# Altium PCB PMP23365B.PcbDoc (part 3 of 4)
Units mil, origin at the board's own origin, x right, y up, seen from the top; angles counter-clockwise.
Board outline 5450 x 2600 mil, 4 copper layers (Top Layer, Signal Layer 1, Signal Layer 2, Bottom Layer), stack 61.2 mil thick; 303 components, 149 nets, 783 pads, 285 vias.
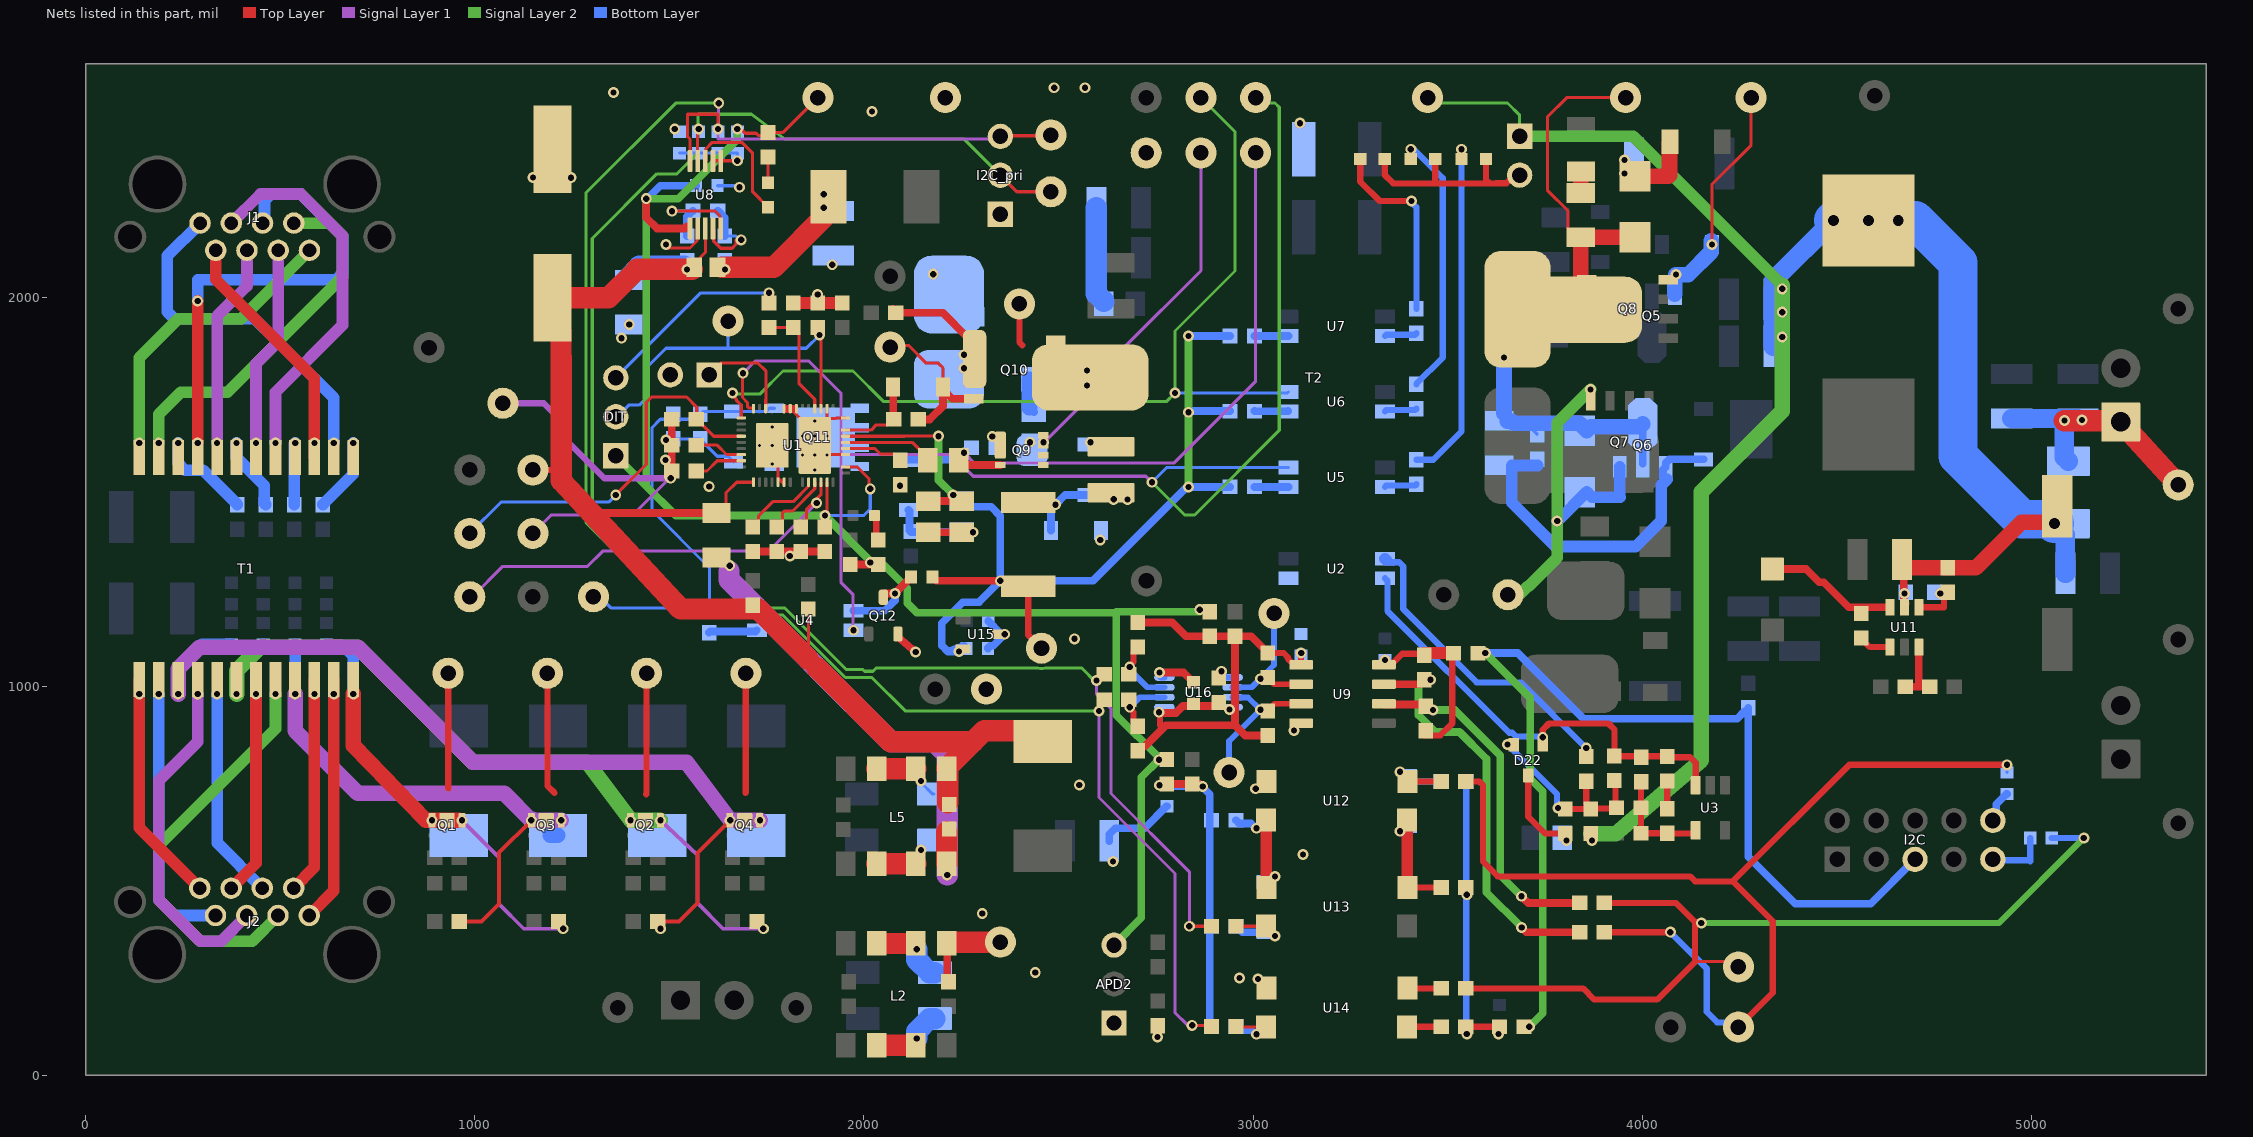
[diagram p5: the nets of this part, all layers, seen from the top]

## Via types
v1: diameter 28, hole 16, Top Layer to Bottom Layer, 261 vias
v2: diameter 19.68, hole 7.87, Top Layer to Bottom Layer, 13 vias
v3: diameter 50, hole 30, Top Layer to Bottom Layer, 7 vias
v4: diameter 50, hole 28, Top Layer to Bottom Layer, 4 vias

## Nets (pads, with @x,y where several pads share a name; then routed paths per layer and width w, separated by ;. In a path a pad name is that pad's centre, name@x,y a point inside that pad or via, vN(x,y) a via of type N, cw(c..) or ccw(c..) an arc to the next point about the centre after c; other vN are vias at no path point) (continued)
NetC31_1: C31.1 Drain_M.1 pad.1@2581.66,1793.73 Q10.5 Q10.6 Q10.7 Q10.8 T2.3 T2.4 | length 109.4
  Top Layer w16: Drain_M.1@2399.67,1982.38 2399.67,1883.48 2407.1,1876.05
  other v1: 2573.44,1773.09 2573.44,1811.67
NetC31_2: C31.2 R122.2 | length 89
  Bottom Layer w20: R122.2@2425.61,1715.82 R122.2@2436.99,1704.44
  Bottom Layer w40: R122.2@2425.61,1715.82 C31.2@2425.61,1788.74
NetC32_1: C32.1 D17.1 Q6.1 R27.1 | length 892.5
  Bottom Layer w8: D17.1@4157.5,1583.03 D17.1@4159.53,1581
  Bottom Layer w20: 4053.48,1521.14 4053.48,1556.45 Q6.1@4060.72,1563.69 4060.72,1573.53 4070.23,1583.03 D17.1@4157.5,1583.03
  Bottom Layer w30: C32.1@3731.35,1567.07 3664.65,1567.07 3664.65,1472.21 3778.01,1358.85 3982.98,1358.85 4048.87,1424.74 4048.87,1516.39 4064.33,1531.85
NetC32_2: C32.2 D12.1 D19.2 Drain_F.1 pad.1@3679.66,1968.61 pad.1@3830,1967.5 Q6.2 Q6.4 Q8.5 Q8.6 Q8.7 Q8.8 R27.2 R29.1 T2.10 T2.11 T2.12 | length 1634.6
  Top Layer w8: R29.1@3842,2153.65 3831.17,2153.65 3809.58,2175.24 3809.58,2221.44 3756.3,2274.72 3756.3,2462.74 3806.06,2512.5 Drain_F.1@3957.5,2512.5
  Top Layer w40: pad.1@3830,1967.5 3842,1972.44 R29.1@3842,2153.65 3842.14,2153.5 3981.54,2153.5 D19.2@3981.68,2153.36
  Bottom Layer w8: R27.2@3644.96,1700.93 3644.96,1682.14 3664.92,1662.18 3715.3,1662.18 3730,1647.48 C32.2@3730,1646.5
  Bottom Layer w20: Q6.2@4001.67,1571.56 Q6.4@4001.67,1673.92
  Bottom Layer w40: R27.2@3644.96,1700.93 v1@3644.96,1842.2 ; R27.2@3653.82,1681.24 3664.65,1681.24 3670.24,1675.65 3838.68,1675.65 3857.5,1656.83 3867.66,1666.99 3994.74,1666.99 Q6.4@4001.67,1673.92
  other v1: 3644.96,1844.49
NetC34_2: C34.2 SST.1 U1.33 | length 1127.7
  Top Layer w8: C34.2@1838.31,1408.99 1853.02,1423.69 1853.02,1455.11 1889.59,1491.69 U1.33@1889.59,1524.28
  Signal Layer 1 w8: SST.1@987.3,1229.93 994.33,1229.93 1072.35,1307.95 1289.84,1307.95 1329.1,1347.21 1754.86,1347.21 v1(1878.63,1470.98)
NetC35_2: C35.2 R29.2 | length 55.1
  Top Layer w40: R29.2@3842,2267.82 3842.09,2267.91 C35.2@3842.66,2322.91
NetC38_1: C38.1 D18.2 Gate_P.1 Q9.4 R31.2 | length 1696.2
  Top Layer w20: C38.1@2243.87,1580.23 2255.67,1568.43 Q9.4@2350.71,1568.43
  Signal Layer 1 w8: v1(2257.57,1599.67) 2283.83,1573.42 2796.61,1573.42 3006.85,1783.66 Gate_P.1@3006.85,2370.57
  Bottom Layer w20: D18.2@2114.59,1581.87 2237.6,1581.87 2255.41,1599.67 v1(2257.57,1599.67)
NetC38_2: C38.2 U1.41 | length 234.3
  Top Layer w8: U1.41@1952.58,1626.64 2123.96,1626.64 2163.87,1586.73 C38.2@2163.87,1580.23
NetC40_2: C40.2 D19.1 R33.1 | length 177.1
  Top Layer w40: D19.1@3981.68,2310.84 4068.5,2310.84 4070.31,2312.64 4070.31,2398.03 C40.2@4071.96,2399.68
  other v1: 3954.64,2317.51 3954.64,2352.18
NetC41_1: C41.1 DIT.2 DTHR.1 U1.3 | length 937.3
  Top Layer w8: C41.1@1881.78,1921.68 1889.59,1913.87 U1.3@1889.59,1713.25
  Bottom Layer w8: DIT.2@1362.5,1692.44 1365.48,1692.44 1395.44,1722.4 1422.6,1722.4 1443.3,1743.1 1443.3,1820.24 1491.43,1868.37 1650.93,1868.37 ; DTHR.1@1650.93,1938.33 1650.93,1868.37 ; v1(1886.03,1902.24) 1852.16,1868.37 1650.93,1868.37
NetC42_2: C42.2 U1.40 | length 153.6
  Top Layer w8: U1.40@1952.58,1610.89 1976.39,1610.89 2028.37,1610.89 2042.62,1596.64 2078.47,1596.64 2093.17,1581.94 C42.2@2093.17,1580.96
NetC44_1: C44.1 C46.1 R47.2 R52.2 U3.4 | length 278.4
  Top Layer w16: C44.1@3997.62,754.74 3997.36,754.48 3997.36,622.59 R52.2@3997.09,622.32 3997.31,622.09 4064.33,622.09 C46.1@4064.55,621.87 4132.8,621.87 4137.6,626.66 U3.4@4137.6,629.74
NetC44_2: C44.2 D22.1 R45.1 R49.1 U2.2 U3.3 | length 1197.7
  Top Layer w16: D22.1@3744.52,849.58 v1(3744.52,868.83) 3744.52,888.09 3760.56,904.13 3913.53,904.13 3928.73,888.94 R45.1@3928.73,820.84 3929.52,820.05 4063.76,820.05 R49.1@4064.55,819.26 4066.07,817.74 4123.13,817.74 4137.6,803.27 U3.3@4137.6,745.89
  Bottom Layer w16: U2.2@3339.02,1277.5 3345.58,1270.93 3345.58,1193.12 3658.46,880.24 3666.19,880.24 3675.31,871.13 3742.23,871.13 v1(3744.52,868.83)
NetC45_2: C45.2 R43.1 | length 66.6
  Top Layer w16: C45.2@2027.32,1438.52 2031.98,1433.86 2031.98,1380.41 R43.1@2036.64,1375.75
NetC46_2: C46.2 R49.2 | length 71.4
  Top Layer w16: C46.2@4064.55,684.86 R49.2@4064.55,756.26
NetC47_1: C47.1 D22.3 R39.1 | length 219
  Top Layer w16: D22.3@3707.12,770.84 3707.12,665.1 3750.8,621.42 R39.1@3802.29,621.42
  other v1: 3805.91,603.62
NetC48_1: C48.1 D26.1 Gate_ex.1 Q11.4 R55.2 R59.2 | length 1170.1
  Bottom Layer w8: Gate_ex.1@1304.91,1229.93 1321.36,1229.93 1349.9,1201.38 1602.3,1201.38 1603.28,1201.38 1603.28,1303.89 1455.37,1451.8 1455.37,1664.48 1476.97,1686.09 1510.38,1686.09 1567.01,1686.09 R59.2@1579.6,1698.68 1586.8,1705.87 D26.1@1664.94,1705.87 1748.69,1705.87 1757.25,1714.44 Q11.4@1770.25,1714.44
NetC49_1: C49.1 R67.1 U8.10 | length 285.5
  Top Layer w8: v1(1507.1,2220.73) 1507.86,2221.48 1617.23,2221.48 1630.08,2208.64 1630.08,2178.23 U8.10@1631.98,2176.32
  Bottom Layer w8: v1(1507.1,2220.73) C49.1@1559.38,2220.73
  Bottom Layer w20: R67.1@1545.74,2156.93 1545.74,2207.1 1559.38,2220.73 1560.13,2221.48 C49.1@1561.12,2221.48
NetC49_2: C49.2 R68.1 U8.9 | length 233.1
  Top Layer w8: U8.9@1612.3,2176.32 1614.2,2174.42 1614.2,2143.21 1631.98,2125.43 1661.31,2125.43 1671.16,2135.28 v1@1671.16,2147.09
  Bottom Layer w8: R68.1@1642.61,2156.93 1670.82,2156.93 1680.66,2147.09 v1(1684.74,2147.09)
  Bottom Layer w20: C49.2@1624.11,2221.48 1625.09,2221.48 1642.61,2203.96 R68.1@1642.61,2156.93
NetC52_1: C52.1 R74.1 R75.1 R94.1 U9.8 | length 459.6
  Top Layer w16: U9.8@3336.3,1055 3355,1055 3383.68,1083.68 3437.14,1083.68 R74.1@3438.7,1085.24 ; R75.1@3438.7,873.5 3481.42,873.5 3512.05,904.13 3512.05,1082.28 R94.1@3515,1085.24
  Top Layer w30: R74.1@3438.7,1085.24 R94.1@3515,1085.24
  other v1: 3339.02,1067.67
NetC53_1: C53.1 C68.1 R26.2 R73.2 R76.2 R89.1 R105.2 R108.2 R109.2 U9.1 U16.1 U16.8 | length 1295
  Top Layer w15: R109.2@2703.8,834.51 2714.89,845.6 2722.5,845.6 ; v1(2758.41,933.02) 2759.94,931.49 2760.9,930.53 2760.9,898.79 2768.29,891.4 ; R73.2@3037.76,1085.24 3078.96,1085.24 3089.56,1074.63 3089.56,1070.44 3105,1055 U9.1@3123.7,1055 v1(3123.7,1085.09)
  Top Layer w20: R108.2@2703.86,1163.7 2792.33,1163.7 2827.79,1128.23 R105.2@2953.7,1128.23 ; 2722.5,845.6 2768.29,891.4 2776.7,899.81 2953.7,899.81 ; v1@2759.94,931.49 2801.96,931.49 2819.72,949.25 R26.2@2903.51,949.25 ; R76.2@3037.76,873.5 2980,873.5 2953.7,899.81 ; R73.2@3037.76,1085.24 3037.76,1086.22 2995.74,1128.23 R105.2@2953.7,1128.23 ; 2953.7,899.81 R105.2@2953.7,1128.23
  other v1: 2939.47,940.14
NetC56_1: C56.1 C57.1 L10.2 OUT.1 VLOAD.1 | length 646.6
  Top Layer w55: v1(5085,1682.5) 5226.55,1682.5 OUT.1@5228.27,1680.77 ; OUT.1@5230,1679.05 OUT.1@5228.27,1680.77 ; VLOAD.1@5377.5,1517.5 5229.92,1678.97 OUT.1@5228.27,1680.77
  Bottom Layer w50: C56.1@4949.52,1688.01 C57.1@5120,1688.01 ; v1(5085,1682.5) 5085,1588.45 L10.2@5095.25,1578.2
  other v1: 5130,1683.96
NetC61_1: C61.1 U11.1 | length 84.2
  Top Layer w16: C61.1@4562.71,1124.1 4562.71,1123.11 4585.27,1100.55 U11.1@4636.59,1100.55
NetC61_2: C61.2 L11.1 U11.6 | length 343
  Top Layer w20: L11.1@4334.46,1301.55 4420.82,1301.55 4455.22,1267.15 4466.91,1267.15 4531.14,1202.92 U11.6@4636.59,1202.92
NetC64_1: C64.1 R95.1 U11.4 | length 106.1
  Top Layer w16: U11.4@4711.39,1202.92 4775.42,1202.92 4775.42,1231.75 R95.1@4784.79,1241.12
  other v1: 4766.09,1238.17
NetC65_1: C65.1 R97.1 R98.1 R102.1 R103.1 R107.2 | length 814.4
  Top Layer w20: R97.1@2778.7,748.5 R107.2@2843.7,748.5 2862.23,748.5 2868.49,742.24 v1(2870.65,742.24)
  Bottom Layer w20: C65.1@2778.7,746.54 2781.46,743.77 2869.12,743.77 v1(2870.65,742.24) 2870.65,740.08 2888.7,722.03 2888.7,130.34 R103.1@2893.5,125.54
  other v1: 2760,745.55
NetC66_1: C66.1 R99.2 R100.2 R101.2 R104.2 | length 778
  Top Layer w8: v1(3630.55,106.3) 3633.5,109.25 R100.2@3633.5,125
  Top Layer w16: R104.2@3546.5,125 R100.2@3633.5,125
  Bottom Layer w16: R101.2@3546.5,755.19 3547.97,753.71 3547.97,107.78 v1(3549.45,106.3)
  Bottom Layer w20: v1(3630.55,106.3) 3632.03,107.78 3632.03,124.51 C66.1@3633.5,125.98
  other v1: 3549.45,463.99
NetD12_2: D12.2 Gate_R.1 Q6.3 Q7.4 | length 925.3
  Top Layer w8: v1(3867.5,1762.84) 3867.5,1733.4 Q7.4@3867.57,1733.32
  Signal Layer 2 w30: Gate_R.1@3670.24,1234.73 3683.77,1234.73 3706.11,1257.08 3708.1,1257.08 3781.57,1330.55 v1(3781.57,1424.27) 3781.57,1676.9 v1(3867.5,1762.84)
  Bottom Layer w30: v1(3781.57,1424.27) 3782.41,1424.27 3857.5,1499.35 3871.22,1485.63 3943.31,1485.63 3942.61,1486.33 Q6.3@3942.61,1563.69
NetD13_2: D13.2 Gate_F.1 Q5.3 Q8.4 | length 604
  Top Layer w8: Q8.4@4071.96,2044.54 4085.25,2057.83 v1(4087,2057.83) ; v1(4179.47,2135) 4179.47,2289.82 4280,2390.35 Gate_F.1@4280,2498.72
  Bottom Layer w40: Q5.3@4084.06,2007.3 4084.06,2042.49 ; v1(4087,2057.83) 4118.99,2057.83 4177.48,2116.31 D13.2@4177.48,2144.53
NetD14_1: D14.1 D15.1 L9.2 | length 234.9
  Top Layer w8: L9.2@2422.41,1472.13 2486.98,1472.13 v1(2492.54,1466.58)
  Bottom Layer w20: D15.1@2480.53,1400.36 2480.53,1454.57 v1(2492.54,1466.58) 2517.65,1491.69 D14.1@2573.44,1491.69
NetD14_2: D14.2 T2.5
  other v1: 2582.05,1626.86
NetD21_1: D21.1 R34.1 U1.43 | length 219.6
  Top Layer w8: U1.43@1952.58,1658.14 2018.53,1658.14 2031.88,1671.49 2062.46,1671.49 R34.1@2076.67,1685.7
  Top Layer w20: D21.1@2074.27,1768.83 2075.47,1767.63 2075.47,1686.89 R34.1@2076.67,1685.7
NetD21_2: D21.2 Gate_M.1 Q10.4 R34.2 | length 426.8
  Top Layer w8: Gate_M.1@2067.44,1871.46 2072.03,1876.05 2114.59,1876.05 2160.34,1830.3 2191.01,1830.3 2203.21,1818.1 D21.2@2203.21,1768.83
  Top Layer w20: R34.2@2139.66,1685.7 2169.19,1685.7 2203.21,1719.72 D21.2@2203.21,1762.82 ; D21.2@2203.21,1768.83 D21.2@2203.21,1762.82 ; Q10.4@2282.3,1738.74 2227.29,1738.74 D21.2@2203.21,1762.82
NetD22_2: D22.2 R36.1 R39.2 R44.2 R45.2 R47.1 | length 507.2
  Top Layer w8: v1(3653.82,850.37) 3654.61,849.58 D22.2@3669.72,849.58
  Top Layer w16: R39.2@3802.29,684.41 R36.1@3867.71,684.41 3867.71,685.4 3856.25,696.86 R44.2@3856.25,756.18 ; R36.1@3869.41,686.11 3927.03,686.11 3931.41,690.5 3931.41,755.17 R45.2@3928.73,757.85
  Bottom Layer w16: v1(3653.82,850.37) 3781.3,722.89 3781.3,689.66 v1(3783.59,687.37)
NetD23_1: D23.1 R60.2 | length 896.2
  Top Layer w8: D23.1@3535.55,2354.89 v1(3535.55,2380)
  Bottom Layer w16: R60.2@3420,1582.05 3463.13,1582.05 3535.55,1654.47 v1(3535.55,2380)
NetD23_2: D23.2 D24.2 D25.2 TPH/TPL/BT.2 | length 535.8
  Top Layer w16: D25.2@3338.43,2354.9 3338.43,2313.71 3360,2292.14 3470.45,2292.14 ; D24.2@3468.48,2354.89 3468.48,2294.11 3470.45,2292.14 ; D23.2@3598.54,2354.89 3598.54,2301.51 3607.92,2292.14 ; TPH/TPL/BT.2@3685.12,2313.38 3672.17,2313.38 3651.27,2292.47 3624.25,2292.47 3623.92,2292.14 3607.92,2292.14 ; 3470.45,2292.14 3607.92,2292.14
NetD24_1: D24.1 R61.2 | length 695.7
  Top Layer w8: D24.1@3405.49,2354.89 v1(3405.49,2380)
  Bottom Layer w16: v1(3405.49,2380) 3413.37,2380 3487.5,2305.87 3487.5,1844.42 3420,1776.92 R61.2@3420,1775.94
NetD25_1: D25.1 R62.2 | length 493
  Top Layer w16: D25.1@3275.43,2354.9 3275.43,2296.66 3325.17,2246.93 v1(3407.27,2246.93)
  Bottom Layer w16: v1(3407.27,2246.93) 3407.27,2243.68 3420,2230.95 R62.2@3420,1969.83
NetD27_1: D27.1 U8.3 | length 325.6
  Top Layer w8: U8.3@1592.61,2349.55 1594.52,2351.45 1594.52,2381.87 1610.1,2397.45 1686.33,2397.45 1714.06,2369.72 1714.06,2270.59 D27.1@1753.54,2231.11
NetD27_2: D27.2 R72.1 | length 74
  Top Layer w8: D27.2@1753.54,2294.11 1753.62,2294.18 R72.1@1753.62,2368.03
NetD29_1: D29.1 R99.1 U12.1 U13.4 | length 260
  Top Layer w8: U13.4@3396.59,483.22 ccw(c3397.89,484.52) U13.4@3397.89,482.69
  Top Layer w16: U13.4@3397.89,482.69 R99.1@3483.5,482.69
  Top Layer w30: U12.1@3395.61,655.72 3396.1,655.23 3396.1,483.72 U13.4@3396.59,483.22
  other v1: 3377.5,627.18
NetD29_2: D29.2 R101.1 R115.2 U12.2 | length 179.1
  Top Layer w16: U12.2@3396.59,755.72 3397.13,755.19 R115.2@3483.5,755.19
  Bottom Layer w16: D29.2@3397.5,769.47 3403.5,769.47 3417.79,755.19 R101.1@3483.5,755.19
  other v1: 3377.5,780
NetD30_1: D30.1 R98.2 U12.4 U13.1 | length 240.4
  Top Layer w30: U12.4@3033.41,655.72 3033.9,655.23 3033.9,483.72 U13.1@3034.39,483.22
  Bottom Layer w20: R98.2@2956.5,655.72 2965.2,647.02 2995.14,647.02 3007.05,635.11 v1(3009.21,635.11) ; D30.1@3028.08,501.39 D30.1@3032.5,496.97
  other v1: 3056.46,511.23
NetD30_2: D30.2 R102.2 R116.1 U13.2 | length 159.2
  Top Layer w8: R116.1@2956.5,383.22 U13.2@3033.41,383.22
  Bottom Layer w20: R102.2@2956.5,383.22 2957.48,383.22 2972.67,368.03 D30.2@3032.5,368.03
  other v1: 3056.46,358.27
NetDIT_3: DIT.3 R30.1 | length 510.6
  Top Layer w8: R30.1@1756.18,1984.68 1756.34,1984.83 v1(1756.34,2010.9)
  Bottom Layer w8: DIT.3@1362.5,1792.44 1580.96,2010.9 v1(1756.34,2010.9)
NetDrain_P_1: Drain_P.1 pad.1@2432.24,1606.16 Q9.5 Q9.6 Q9.7 Q9.8 R122.1 | length 912.4
  Signal Layer 1 w8: v1(2461.83,1626.86) 2463.8,1626.86 2667.76,1830.81 2667.76,1869.4 2866.17,2067.8 Drain_P.1@2866.17,2370.57
  other v1: 2427.17,1626.86
NetEMPS_1: EMPS.1 U1.11 | length 256.5
  Top Layer w8: EMPS.1@1602.5,1800 1633.47,1830.97 1726.76,1830.97 1748.73,1808.99 1748.73,1737.94 1747.86,1737.07 U1.11@1747.86,1721.07
NetI2C_9: I2C.9 R92.1 | length 158.2
  Bottom Layer w16: I2C.9@4901.24,555 4903.74,552.5 4994.88,552.5 4997.38,550 R92.1@4997.38,610
NetI2C_10: I2C.10 R93.2 | length 83.8
  Bottom Layer w20: I2C.10@4901.24,655 4909.84,663.6 4909.84,696.58 4936.52,723.25 R93.2@4937.5,723.25
NetJ1_1: J1.1 T1.2 | length 898.8
  Bottom Layer w30: J1.1@294.21,2190.08 210,2105.87 210,1961.94 227.57,1944.36 435.06,1944.36 637.95,1741.46 v1(637.95,1625)
NetJ1_2: J1.2 T1.3 | length 637.5
  Top Layer w30: J1.2@334.37,2120 334.37,2045.05 587.95,1791.46 v1(587.95,1625) T1.3@587.95,1587.5
NetJ1_3: J1.3 T1.5 | length 964.9
  Signal Layer 1 w30: J1.3@374.53,2190.08 449.45,2265 552.62,2265 660,2157.62 660,1927.53 487.95,1755.48 v1(487.95,1625)
NetJ1_4: J1.4 T1.8 | length 526.8
  Signal Layer 1 w30: v1(337.95,1625) 337.95,1951.65 414.69,2028.39 J1.4@414.69,2120
NetJ1_5: J1.5 T1.9 | length 1207.4
  Top Layer w30: v1(287.95,1625) v1(287.95,1990)
  Bottom Layer w30: v1(287.95,1990) 287.95,2044.71 643.55,2044.71 661.12,2062.29 661.12,2156.5 552.62,2265 477.22,2265 459.65,2247.43 459.65,2194.88 J1.5@454.84,2190.08
NetJ1_6: J1.6 T1.6 | length 518.6
  Signal Layer 1 w30: v1(437.95,1625) 437.95,1828.73 495,1885.78 J1.6@495,2120
NetJ1_7: J1.7 T1.11 | length 936.7
  Signal Layer 2 w30: v1(187.95,1625) 187.95,1698.63 244.8,1755.48 364.7,1755.48 660,2050.78 660,2157.62 627.54,2190.08 J1.7@535.16,2190.08
NetJ1_8: J1.8 T1.12 | length 770.9
  Signal Layer 2 w30: v1(137.95,1625) 137.95,1844.36 237.95,1944.36 399.68,1944.36 J1.8@575.32,2120
NetJ2_1: J2.1 T1.23 | length 632.7
  Top Layer w30: J2.1@574.76,410.9 637.95,474.09 T1.23@637.95,1017.42
  other v1: 637.95,980
NetJ2_2: J2.2 T1.22 | length 558.5
  Top Layer w30: J2.2@534.61,480.98 587.95,534.33 T1.22@587.95,1017.42
  other v1: 587.95,980
NetJ2_3: J2.3 T1.20 | length 1030.5
  Signal Layer 2 w30: v1(487.95,980) 487.95,890.69 187.95,590.69 187.95,451.73 294.68,345 428.55,345 J2.3@494.45,410.9
NetJ2_4: J2.4 T1.17 | length 547.2
  Bottom Layer w30: v1(337.95,980) 337.95,597.32 J2.4@454.29,480.98
NetJ2_5: J2.5 T1.16 | length 867.4
  Signal Layer 1 w30: v1(287.95,980) 287.95,857.24 187.95,757.24 187.95,451.73 294.68,345 348.23,345 J2.5@414.13,410.9
NetJ2_6: J2.6 T1.19 | length 562.9
  Top Layer w30: J2.6@373.98,480.98 437.95,544.96 T1.19@437.95,1017.42
  other v1: 437.95,980
NetJ2_7: J2.7 T1.14 | length 697.9
  Bottom Layer w30: v1(187.95,980) 187.95,451.73 228.89,410.79 333.71,410.79 J2.7@333.82,410.9 J2.7@329.01,415.71
NetJ2_8: J2.8 T1.13 | length 600.9
  Top Layer w30: T1.13@137.95,1017.42 137.95,636.69 J2.8@293.66,480.98
  other v1: 137.95,980
NetL1_1: L1.1 L2.4 R9.2 | length 161.9
  Top Layer w55: R9.2@2047.48,76.99 L1.1@2130.67,76.99
  Bottom Layer w55: v1(2135.62,94.73) 2135.62,112.82 2168.74,145.94 L2.4@2182.52,145.94
NetL2_3: L2.3 L3.1 R12.2 | length 170.5
  Top Layer w55: R12.2@2047.48,338.88 L3.1@2130.67,338.88
  Bottom Layer w55: v1(2135.62,323.87) 2135.62,297.18 2168.74,264.06 L2.3@2182.52,264.06
NetL4_1: L4.1 L5.3 R13.2 | length 186.6
  Top Layer w8: L4.1@2133.09,788.36 2146.99,774.46 v1(2146.99,756.51)
  Top Layer w55: R13.2@2033.33,788.36 L4.1@2133.09,788.36
  Bottom Layer w8: v1(2146.99,756.51) 2146.99,752.67 2177.13,722.53 L5.3@2179.87,722.53
NetL5_4: L5.4 L6.1 R18.2 | length 141.5
  Top Layer w8: L6.1@2133.09,543.47 2146.99,557.37 v1(2146.99,579.46)
  Top Layer w55: R18.2@2033.33,543.47 L6.1@2133.09,543.47
NetQ10_1: pad.1@2218.74,1788.74 pad.1@2284.49,1840.81 Q10.1 Q10.2 Q10.3 R40.2 R42.2 R120.2 | length 246.3
  Top Layer w20: R40.2@2075.34,1969.67 2080.11,1964.91 2080.11,1959.99 2203.15,1959.99 2267.3,1895.84 2267.3,1890.75 2269.31,1888.74 Q10.1@2282.3,1888.74
  other v1: 2257.01,1817.17 2257.01,1851.84
NetQ12_3: Q12.3 R54.1 U4.1 | length 233.3
  Top Layer w20: Q12.3@2049.94,1228.63 2049.94,1236.5 2051.76,1238.31 v1(2079.68,1238.31) 2121.02,1279.66 R54.1@2121.02,1280.64
  Bottom Layer w20: U4.1@1972.98,1193.98 2053.2,1193.98 2079.68,1220.45 v1(2079.68,1238.31)
NetR5_1: R5.1 T1.10 | length 248.4
  Bottom Layer w30: v1(237.95,1625) 237.95,1572.57 255.53,1555 301.87,1555 389.39,1467.48 R5.1@389.39,1466.5
NetR6_1: R6.1 T1.7 | length 190.5
  Bottom Layer w30: v1(387.95,1625) 387.95,1587.05 459.22,1515.78 459.22,1470.2 R6.1@462.92,1466.5 R6.1@462.92,1467.48
NetR7_1: R7.1 T1.4 | length 159.3
  Bottom Layer w30: R7.1@536.46,1466.5 536.46,1622.96 v1(538.5,1625)
NetR8_1: R8.1 T1.1 | length 190.8
  Bottom Layer w30: R8.1@610,1466.5 610,1467.48 687.95,1545.43 v1(687.95,1625)
NetR26_1: R26.1 U16.5 | length 37.5
  Bottom Layer w15: v1(2919.02,1038.54) 2921.5,1036.06 2921.5,1031.91 2930.59,1022.82 U16.5@2947.57,1022.82
NetR30_2: R30.2 R32.2 U1.4 | length 293.9
  Top Layer w8: R30.2@1756.18,1921.68 R32.2@1818.95,1921.68 1833.65,1906.98 1833.65,1777.26 1873.84,1737.07 U1.4@1873.84,1713.25
NetR35_2: R35.2 REF.1 U1.17 | length 995.8
  Top Layer w8: v1(1362.5,1491.69) 1440.72,1569.91 1440.72,1729.16 1454.67,1743.1 1544.51,1743.1 1570.48,1717.13 1570.48,1686.09 1614.18,1642.39 U1.17@1684.87,1642.39
  Bottom Layer w8: REF.1@987.3,1392.85 1067.59,1473.14 1343.95,1473.14 v1(1362.5,1491.69)
NetR37_2: R37.2 U1.21 | length 126.3
  Top Layer w8: R37.2@1569.49,1553.11 1596.98,1553.11 1623.27,1579.4 U1.21@1684.87,1579.4
NetR38_2: R38.2 U1.20 | length 125.6
  Top Layer w8: R38.2@1569.49,1619.6 1622.8,1619.6 1647.12,1595.27 1684.74,1595.27 U1.20@1684.87,1595.14 U1.20@1684.87,1595.27
NetR44_1: R44.1 U2.1 | length 804.7
  Top Layer w8: R44.1@3856.25,819.17 v1(3856.25,841.02)
  Bottom Layer w16: U2.1@3341.73,1324.78 3347.81,1318.71 3375.47,1318.71 3386.24,1307.95 3386.24,1198.44 3574.79,1009.89 3687.38,1009.89 v1(3856.25,841.02)
  Bottom Layer w30: U2.1@3339.02,1327.5 U2.1@3341.73,1324.78
NetR48_1: R48.1 U1.31 | length 205.4
  Top Layer w8: R48.1@1714.88,1408.99 1729.58,1423.69 1729.58,1437.78 1766.1,1474.3 1818.36,1474.3 1857.84,1513.78 1857.84,1524.28 U1.31@1858.1,1524.28
NetR50_2: R50.2 U1.32 | length 168.1
  Top Layer w8: R50.2@1776.63,1408.99 1790.41,1422.77 1790.41,1445.26 1795.09,1449.94 1816.45,1449.94 1873.72,1507.21 1873.72,1524.15 U1.32@1873.84,1524.28
NetR55_1: R55.1 U4.3 | length 125.2
  Bottom Layer w20: R55.1@1602.3,1137.76 1605.41,1140.87 1721.84,1140.87 U4.3@1724.95,1143.98
NetR60_1: R60.1 U5.4 | length 83.8
  Bottom Layer w16: U5.4@3339.02,1512.22 3342.43,1515.64 3416.58,1515.64 R60.1@3420,1519.06
NetR61_1: R61.1 U6.4 | length 83.8
  Bottom Layer w16: U6.4@3339.02,1706.11 3342.43,1709.53 3416.58,1709.53 R61.1@3420,1712.95
NetR62_1: R62.1 U7.4 | length 83.8
  Bottom Layer w16: U7.4@3339.02,1900 3342.43,1903.42 3416.58,1903.42 R62.1@3420,1906.84
NetR63_1: R63.1 U5.1 | length 87.1
  Bottom Layer w20: R63.1@3003.9,1512.22 U5.1@3090.98,1512.22
NetR64_1: R64.1 U6.1 | length 87.8
  Bottom Layer w8: U6.1@3090.15,1706.94 U6.1@3090.98,1706.11
  Bottom Layer w20: R64.1@3003.9,1706.94 3004.31,1706.53 3089.73,1706.53 U6.1@3090.15,1706.94
NetR65_1: R65.1 U7.1 | length 87.1
  Bottom Layer w20: R65.1@3003.9,1900 U7.1@3090.98,1900
NetR74_2: R74.2 R106.1 U9.7 | length 1071.8
  Top Layer w20: U9.7@3336.3,1005 3428.89,1005 3439.9,1016.01 R74.2@3439.9,1016.99 ; v1(3690.33,380.22) 3702.51,368.03 R106.1@3839.59,368.03
  Signal Layer 2 w20: v1@3458.6,1014.04 v1(3456.06,1016.58) 3439.49,1016.58 3425.6,1002.69 3425.6,925.4 3468.48,882.52 3530.72,882.52 3599.78,813.46 3599.78,470.77 v1(3690.33,380.22)
NetR75_2: R75.2 R121.1 U9.6 | length 872.6
  Top Layer w20: U9.6@3336.3,955 3338.11,953.19 3439.58,953.19 R75.2@3444.16,948.61 ; v1(3689.72,460.39) 3707.1,443.01 R121.1@3839.59,443.01
  Signal Layer 2 w20: v1(3462.86,938.77) 3518.72,938.77 3635.55,821.94 3635.55,514.57 v1(3689.72,460.39)
NetR80_1: R80.1 R81.1 R82.1 R83.1 U8.1 U8.2 | length 231.6
  Top Layer w8: U8.2@1612.3,2349.55 1612.96,2350.21 v1(1674.88,2350.21)
  Bottom Layer w8: R83.1@1525.8,2369.89 R82.1@1575.5,2369.89 R81.1@1625.19,2369.89 R80.1@1674.88,2369.89 v1(1674.88,2350.21)
NetR88_1: R88.1 R96.2 U11.3 | length 164.8
  Top Layer w20: R88.1@4676.5,998.7 4710.59,998.7 ; U11.3@4711.39,1100.55 4710.59,1099.75 4710.59,998.7 ; R96.2@4739.07,998.7 4710.59,998.7
NetR103_2: R103.2 R118.1 U14.4 | length 138.6
  Top Layer w8: R118.1@2956.5,125.54 2958.14,123.89 U14.4@3033.41,123.89
  Bottom Layer w20: R103.2@2956.5,125.54 2965.2,116.84 2995.75,116.84 3007.05,105.54 v1(3009.21,105.54)
NetR104_1: R104.1 U14.1 | length 88.2
  Top Layer w8: U14.1@3395.61,123.89 cw(c3398.29,121.21) U14.1@3398.29,125
  Top Layer w16: U14.1@3398.29,125 R104.1@3483.5,125
NetR108_1: R108.1 R111.2 U16.3 | length 167.3
  Top Layer w15: v1(2683.26,1049.65) 2683.26,1053.17 2692.66,1062.57 2692.66,1089.5 R108.1@2703.86,1100.7
  Bottom Layer w15: v1@2683.26,1042.02 2728.06,997.23 U16.3@2772.38,997.23
NetR109_1: R109.1 R110.1 U16.2 | length 176.7
  Top Layer w15: R110.1@2680.31,964.75 2681.79,963.27 2681.79,947.53 v1(2683.26,946.05) 2683.26,942.53 2692.6,933.2 2692.6,908.7 R109.1@2703.8,897.5
  Bottom Layer w15: v1(2683.26,946.05) 2708.85,971.64 U16.2@2772.38,971.64
NetR117_1: R117.1 U14.2 | length 87.1
  Top Layer w8: U14.2@3396.59,223.89 U14.2@3397.13,223.35
  Top Layer w16: U14.2@3397.13,223.35 R117.1@3483.5,223.35
PGND: APD2.1 C8.2 C9.1 C16.2 C20.2 C21.2 C22.2 C23.2 C24.2 C25.2 C30.2 C34.1 C36.2 C37.2 C39.1 C41.2 C42.1 C43.2 C51.2 C53.2 C65.2 C67.2 C68.2 C70.2 D15.2 D18.1 EMPS.2 I2C_pri.1 L3.2 pad.1@2218.74,2006.57 pad.1@2350.71,1619.61 Q9.1 Q9.2 Q9.3 Q11.5 Q11.6 Q11.7 Q11.8 Q11.9 Q12.2 R11.1 R31.1 R32.1 R42.1 R48.2 R50.1 R53.1 R83.2 R120.1 RTN1.1 RTN2.1 RTN3.1 RTN4.1 T2.6 U1.2 U1.7 U1.8 U1.9 U1.39 U1.45 U1.46 U2.3 U8.7 U9.4 U12.3 U14.3 U15.3 U16.4 | length 2169.9
  Top Layer w8: v1@1498.49,2126.24 1553.27,2126.24 1571.02,2144 1571.02,2174.42 U8.7@1572.93,2176.32 ; 1819.5,1712.5 1819.5,1704.61 U1.46@1873.84,1650.26 ; U1.46@1901.99,1646.92 1905.34,1650.26 U1.46@1905.34,1681.76 ; U1.2@1905.34,1713.25 U1.46@1905.34,1681.76 ; U1.39@1952.58,1595.14 1897.47,1595.14 U1.46@1873.84,1618.77 v2(1873.84,1643.37) U1.46@1873.84,1650.26 ; U1.45@1952.58,1689.63 1929.21,1689.63 1927.18,1687.6 1911.18,1687.6 U1.46@1905.34,1681.76 ; L3.2@2213.09,338.88 L3.2@2216.63,342.42 ; U1.46@1873.84,1650.26 U1.46@1905.34,1681.76
  Top Layer w20: R48.2@1714.88,1346 R50.1@1776.63,1346 C34.1@1838.31,1346 C39.1@1900,1346 ; 1802.5,1712.5 1819.5,1712.5 ; Q12.2@2087.35,1134.14 2087.35,1126.26 v1(2133.09,1088.19) ; C37.2@2165.49,1395.67 C30.2@2252.1,1395.67 ; L3.2@2214.04,335.51 2214.04,243.74 C8.2@2217.41,240.38 ; v1(2760,1035.29) 2760.25,1035.04 2821.63,1035.04 2846.55,1010.12 C53.2@2847.53,1010.12 ; v1(3006.85,736.49) 3008.38,738.02 3018.8,738.02 3034.39,753.61 U12.3@3034.39,755.72
  Top Layer w30: R32.1@1818.95,1984.68 C43.2@1944.54,1984.67
  Top Layer w55: L3.2@2216.63,342.42 RTN1.1@2350.71,342.42
  Bottom Layer w8: C51.2@1623.72,2286.23 1676.72,2286.23 v1(1680.66,2282.3)
  Bottom Layer w15: v1(2760,1035.29) 2762.49,1032.8 2762.49,1024.08 2763.74,1022.82 U16.4@2772.38,1022.82
  Bottom Layer w20: D18.1@2114.59,1452.93 2117.32,1450.21 2117.32,1400.13 R53.1@2120.04,1397.4 2120.99,1396.46 2251.16,1396.46 C36.2@2252.1,1395.51 ; C67.2@2319.13,1097.09 2319.13,1098.07 2324.88,1103.82 2332.19,1103.82 v1(2361.81,1133.44) 2360.28,1134.97 2352.04,1134.97 2319.56,1167.45 C70.2@2319.56,1168.44 ; C25.2@2616.93,1982.38 C25.2@2616.93,1988.88 ; C9.1@2630.53,602.45 2630.53,619.52 2646.12,635.11 2721.41,635.11 2777.72,691.42 C65.2@2778.7,691.42
  Bottom Layer w55: C23.2@2597.6,2229.15 C24.2@2597.6,2100.65 2597.6,2008.2 C25.2@2616.93,1988.88
  other v1: 2754.9,98.35 3013.03,247.8 2965.2,249.9 2440.32,264.06 2304.17,416.04 2640.37,549.3 3128.39,567.38 2553.76,746 3105,886.3 2541.49,1121.71 1809.77,1334.41 2607.45,1375.75 2280.65,1395.67 2641.84,1480.19 2677.56,1480.15 2093.17,1515.01 2329.84,1641.4 1377.35,1894.36 1397.04,1929.8 1881.3,2006.57 2178.28,2058.86 1918.7,2083.15 1491.68,2135.28 1150,2307.5 1247.5,2306.9 1514.06,2431.9 3120.51,2446.93 2020.82,2476.71 1356.35,2525.46 2489.04,2537.8 2567.98,2537.8
  other v2: 1873.84,1555.77 1842.15,1594.16 1873.84,1594.16 1905.54,1594.16 1842.15,1643.37 1905.54,1643.37 1873.84,1681.76
PR12: C1.1 D2.2 PR12.1 Q1.1 Q1.2 Q1.5 Q1.6 Q1.8 R15.2 T1.24 | length 1404.8
  Top Layer w16: PR12.1@931.66,1033.35 931.66,738.44 932.55,737.55
  Top Layer w40: v1(687.95,980) 687.95,847.05 874.75,655.34 v1(890.43,655.34) Q1.8@928.81,655.34 v1@958.81,655.34
  Signal Layer 1 w10: v1(967.2,655.34) 1062.5,560.04 1062.5,440 1125.86,376.64 v1(1227.18,376.64)
  Bottom Layer w30: C1.1@619.68,1107.44 620.43,1106.69 658.86,1106.69 687.95,1077.6 v1(687.95,980)
PR36: C2.1 D3.2 PR36.1 Q3.1 Q3.2 Q3.5 Q3.6 Q3.8 R14.2 T1.21 | length 1711
  Top Layer w10: R14.2@960.31,395.34 1017.84,395.34 1062.5,440 1062.5,572.41 v1(1145.43,655.34)
  Top Layer w16: PR36.1@1186.66,1033.35 1186.66,744.13 1205.2,725.6
  Signal Layer 1 w40: v1(538.5,980) 538.5,885.54 699.45,725 1075.77,725 v1(1145.43,655.34) ; v1@1148.38,658.29 v1(1145.43,655.34) ; v1(1222.2,655.34) v1(1145.43,655.34)
  Bottom Layer w30: C2.1@538.12,1107.44 538.5,1107.05 v1(538.5,980)
  Bottom Layer w40: D3.2@1193.81,616.75 D3.2@1213.81,616.75
PR45: C3.1 D4.2 PR45.1 Q2.1 Q2.2 Q2.5 Q2.6 Q2.8 R17.2 T1.18 | length 2290
  Top Layer w16: 1440.72,722.53 1441.66,723.47 PR45.1@1441.66,1033.35
  Signal Layer 1 w10: v1(1477.2,655.34) 1572.5,565.81 1572.5,442.5 1638.36,376.64 v1(1741.6,376.64)
  Signal Layer 2 w40: v1(387.95,980) 387.95,1039.82 448.68,1100.55 699.45,1100.55 995,805 1289.15,805 v1(1400.43,655.34) v1(1477.2,655.34)
  Bottom Layer w30: v1(387.95,980) 387.95,1039.82 455.57,1107.44 C3.1@456.56,1107.44
PR78: C4.1 D5.2 PR78.1 Q4.1 Q4.2 Q4.5 Q4.6 Q4.8 R16.2 T1.15 | length 2685.9
  Top Layer w10: R16.2@1470.31,395.34 1525.34,395.34 1572.5,442.5 1572.5,571.41 v1(1656.43,655.34)
  Top Layer w16: 1695.8,725.87 1696.66,726.73 PR78.1@1696.66,1033.35
  Signal Layer 1 w40: v1(237.95,980) 237.95,1045.28 293.22,1100.55 699.45,1100.55 995,805 1544.15,805 v1(1656.43,655.34) v1(1733.2,655.34)
  Bottom Layer w30: v1(237.95,980) 237.95,1045.28 300.11,1107.44 C4.1@375,1107.44
  other v1: 1477.11,376.64
SCL_at_pri: I2C_pri.3 R81.2 R110.2 R118.2 SCL_at_pri.1 U8.5 | length 4981.3
  Top Layer w8: U8.5@1553.24,2349.55 1553.24,2406.3 1546.47,2413.07 1546.47,2469.82 1625,2469.82 v1(1625.19,2431.9) ; I2C_pri.3@2350.71,2413.07 2352.25,2414.61 2478.99,2414.61 SCL_at_pri.1@2480.53,2416.15 ; v1(2843.7,128.49) 2890.55,128.49 R118.2@2893.5,125.54
  Top Layer w15: v1(2604.15,936.61) 2606.63,939.1 2606.63,954.07 R110.2@2617.32,964.75
  Signal Layer 1 w8: v1(1627.08,2498.26) 1626.14,2497.31 1626.14,2432.85 v1(1625.19,2431.9) 1625.19,2406.3 1655.26,2406.3 1655.53,2406.02 2223.28,2406.02 2223.56,2406.3 2343.94,2406.3 I2C_pri.3@2350.71,2413.07 ; v1(2604.15,936.61) 2604.15,714.13 2799.37,518.9 2799.37,160.97 v1@2831.85,128.49
  Signal Layer 2 w8: v1(1627.08,2498.26) 1516.38,2498.26 1286.12,2267.99 1286.12,1420.48 1523.92,1182.68 1792.3,1182.68 1952.52,1022.46 2020.34,1022.46 2106.2,936.61 v1(2604.15,936.61)
SCL_at_pri_iso: R76.1 SCL_pri_raw.1 U9.3 U16.7 | length 373.4
  Top Layer w15: R76.1@3037.76,936.5 3037.76,937.48 3055.28,955 U9.3@3123.7,955
  Bottom Layer w15: SCL_pri_raw.1@2938.71,778.33 2938.71,859.1 v1(3019.06,939.45) 2987.38,971.12 2948.09,971.12 U16.7@2947.57,971.64
SCL_pri: R92.2 R117.2 R121.2 SCL_pri.1 | length 2274.7
  Top Layer w8: 4135.93,292.32 4233.92,292.32 SCL_pri.1@4247.5,278.74
  Top Layer w16: R117.2@3546.5,223.35 3848.1,223.35 3876.64,194.81 4038.42,194.81 4135.93,292.32 4135.93,391.24 ; R121.2@3902.58,443.01 4086.62,443.01 4136.09,393.54 4149.76,393.54 v1(4152.05,391.24)
  Signal Layer 2 w16: v1(4152.05,391.24) 4916.24,391.24 v1(5135,610)
  Bottom Layer w16: R92.2@5052.5,610 v1@5125,610
SDA_at_pri: I2C_pri.2 R82.2 R111.1 R116.2 SDA_at_pri.1 U8.4 | length 4492.7
  Top Layer w8: U8.4@1572.93,2349.55 v1@1572.93,2418.43 ; I2C_pri.2@2350.71,2313.07 2393.19,2270.59 SDA_at_pri.1@2480.53,2270.59 ; v1(2836.3,383.22) R116.2@2893.5,383.22
  Signal Layer 1 w8: v1(2597.84,1014.37) 2597.84,979.51 2635.06,942.3 2635.06,724.29 2836.3,523.05 v1(2836.3,383.22)
  Signal Layer 2 w8: 1572.93,2396.78 1572.93,2369.89 1519.77,2316.73 1468.01,2316.73 1301.99,2150.72 1301.99,1427.06 1527.67,1201.38 1796.05,1201.38 1954.52,1042.91 1997.41,1042.91 2001.98,1038.34 2023.42,1038.34 2031.75,1046.67 2446.72,1046.67 ccw(c2456.4,1097.63) 2466.08,1046.67 2560.13,1046.67 2562.47,1044.33 2592.43,1014.37 v1(2597.84,1014.37) ; 1572.93,2397.45 v1@1573.6,2419.1 ; v1@1573.6,2425.12 1573.6,2469.82 1708.9,2469.82 1711.56,2469.82 1797.07,2406.02 2257.76,2406.02 I2C_pri.2@2350.71,2313.07
  other v1: 1575.5,2431.9
SDA_at_pri_iso: R73.1 SDA_pri_raw.1 U9.2 U16.6 | length 356.6
  Top Layer w15: R73.1@3037.76,1022.24 3037.76,1021.26 3054.02,1005 U9.2@3123.7,1005
  Bottom Layer w15: U16.6@2947.57,997.23 2996.65,997.23 3018.71,1019.29 v1(3019.06,1019.29) 3054.02,1054.25 SDA_pri_raw.1@3054.02,1187.14
SDA_pri: R93.1 R106.2 R115.1 SDA_pri.1 | length 2720.9
  Top Layer w16: R115.1@3546.5,755.19 3581.46,755.19 3591.09,745.55 3591.09,549.3 3629.16,511.23 4123.13,511.23 4135.93,498.44 4233.27,498.44 ; R106.2@3902.58,368.03 v1(4072.46,368.03) ; SDA_pri.1@4247.5,123.89 4335.73,212.12 4335.73,395.98 4233.27,498.44 ; v1(4937.5,798.05) 4532.89,798.05 4233.27,498.44
  Bottom Layer w8: R93.1@4937.5,778.37 v1(4937.5,798.05)
  Bottom Layer w16: v1(4072.46,368.03) 4165.91,274.59 4165.91,163.22 4192.99,136.14 4235.25,136.14 SDA_pri.1@4247.5,123.89
TPH: TPH.1 U1.13 U4.2 U5.2 | length 3565.6
  Top Layer w8: v1(1689.6,1804.53) 1688.01,1802.94 1688.01,1741.89 1700.74,1729.16 1700.74,1719.32 1705.43,1714.63 1716.3,1714.63 1716.36,1714.57 U1.13@1716.36,1713.25
  Signal Layer 1 w8: v1(1689.6,1804.53) 1720.35,1835.28 1859.1,1835.28 1940.77,1753.61 1940.77,1595.14 ; v1@1971.66,1157.29 1971.66,1236.49 1940.77,1267.37 1940.77,1595.14 ; v1(2740.32,1524.15) 2724.77,1539.7 2280.96,1539.7 2225.51,1595.14 1940.77,1595.14
  Signal Layer 2 w8: v1(2740.32,1524.15) 2824.47,1440 2850,1440 3067.5,1657.5 3067.5,2487.81 3056.59,2498.72 3020.63,2498.72 TPH.1@3006.85,2512.5
  Bottom Layer w8: v1(2740.32,1524.15) 2778.38,1562.22 U5.2@3090.98,1562.22
  other v1: 1973.06,1143.9
TPL: TPL.1 U1.14 U6.2 | length 2429.2
  Top Layer w8: v1(1662.14,1753.61) 1662.14,1748.2 1672.14,1738.2 1672.14,1735.31 1684.87,1722.58 U1.14@1684.87,1689.63
  Signal Layer 2 w8: v1(1662.14,1753.61) 1664.36,1751.39 1733.58,1751.39 1792.06,1809.87 1972.11,1809.87 2050.64,1731.34 2777.1,1731.34 v1(2799.37,1753.61) 2799.37,1912.86 2953.7,2067.19 2953.7,2424.97 TPL.1@2866.17,2512.5
  Bottom Layer w8: v1(2799.37,1753.61) 3088.48,1753.61 U6.2@3090.98,1756.11
V5_REG: I2C.5 R94.2 R100.1 R123.1 | length 2712.8
  Signal Layer 2 w20: v1(3597.07,1085.24) 3712.65,969.65 3712.65,761.86 3744.52,729.98 3744.52,159.52 v1(3710,125) v1@3699.45,125
  Bottom Layer w20: v1(3597.07,1085.24) 3680.11,1085.24 3849.18,916.16 4244.25,916.16 4263.05,934.96 4264.04,934.96 4272.74,943.66 R123.1@4272.74,944.64 4272.74,561.9 4393.63,441.01 4587.25,441.01 I2C.5@4701.24,555
VB: APD2.3 C39.2 C51.1 DIT.1 R43.2 R46.2 R72.2 R80.2 R89.2 R97.2 U1.34 U1.37 U8.6 VB.1 | length 4744.9
  Top Layer w8: v1@1682.82,2433.82 1695.55,2421 1723.16,2421 1728.88,2415.27 R72.2@1753.62,2415.27 ; R72.2@1753.62,2423.15 1792.43,2423.15 VB.1@1881.78,2512.5 ; C39.2@1905.21,1414.2 1905.21,1524.28 U1.34@1905.34,1524.28 ; U1.37@1952.58,1563.65 1952.71,1563.52 1982.95,1563.52 2013.26,1533.21 2013.26,1510.29 v1(2016.35,1507.21) ; v1(2758.41,811.14) 2778.35,811.14 R97.2@2778.7,811.5 ; v1(2863.25,1196.77) 2883.16,1196.77 R89.2@2888.7,1191.22
  Top Layer w20: v1(1440.72,2252.86) 1440.72,2204.24 1468.64,2176.32 1540.05,2176.32 1545.74,2182.01 ; R46.2@1964.87,1312.76 R43.2@2036.64,1312.76
  Signal Layer 2 w20: DIT.1@1362.5,1592.44 1439.46,1515.48 ; v1@1674.88,2425.01 1674.88,2404.8 1522.93,2252.86 v1(1440.72,2252.86) 1440.72,1516.74 1439.46,1515.48 ; v1(2016.35,1318.03) 2017.28,1317.1 2045.96,1317.1 2111.55,1251.51 2111.55,1213.74 2136.42,1188.88 2648.81,1188.88 ; v1@2018.42,1320.1 v1(1900,1438.52) 1516.42,1438.52 1439.46,1515.48 ; APD2.3@2642.93,334.71 2713,404.77 2713,765.73 v1(2758.41,811.14) ; v1@2760,814.45 2648.81,925.64 2648.81,1191.22 v1@2863.25,1191.22
  Bottom Layer w8: v1(1900,1438.52) 1999.76,1438.52 2016.35,1455.1 v1(2016.35,1507.21)
  Bottom Layer w20: v1@1446.95,2256.16 1477.02,2286.23 C51.1@1568.61,2286.23
  other v1: 1674.88,2431.9
VCC: C30.1 C36.1 C37.1 C67.1 L9.1 R54.2 R63.2 R64.2 R65.2 U1.42 U15.2 VCC.1 | length 2860.5
  Top Layer w8: U1.42@1952.58,1642.39 1952.71,1642.26 2104.76,1642.26 2104.76,1642.51 v1(2191.89,1642.51) ; v1(2350.71,1270.84) 2364.38,1257.17 L9.1@2422.41,1257.17
  Top Layer w16: L9.1@2422.41,1257.17 2422.41,1131.63 VCC.1@2456.4,1097.63 VCC.1@2456.4,1080.32
  Top Layer w20: C37.1@2165.49,1475.67 C30.1@2252.1,1475.67 ; R54.2@2176.14,1280.64 2176.14,1279.66 2181.89,1273.91 2182.87,1273.91 2185.95,1270.84 v1(2350.71,1270.84)
  Signal Layer 2 w20: v1(2191.89,1642.51) 2191.89,1529.26 v1(2229.46,1491.69) ; v1(2834.12,1512.22) v1(2834.12,1703.99) v1(2834.12,1900)
  Bottom Layer w20: v1(2244.33,1089) 2216.31,1089 ; C36.1@2252.1,1475.51 2266.51,1461.1 2326.89,1461.1 2350.71,1437.28 v1(2350.71,1270.84) ; C67.1@2257.13,1104.19 2216.31,1089 ; v1(2834.12,1703.99) 2836.28,1703.99 2839.24,1706.94 R64.2@2940.91,1706.94 ; v1(2834.12,1900) R65.2@2940.91,1900 ; R63.2@2940.91,1512.22 2831.95,1512.22 2827.95,1508.22 2826.12,1508.22 2588.74,1270.84 v1(2350.71,1270.84) ; 2216.31,1089 2200.33,1104.98 2200.33,1162.09 2253.94,1215.7 2295.57,1215.7 v1(2350.71,1270.84)
VDD: C11.1 C20.1 C21.1 C33.1 D1.1 L4.2 R41.1 R51.2 R66.1 R67.2 U1.23 U8.8 VDD.1 | length 3587.7
  Top Layer w8: R66.1@1558.74,2071.12 R66.1@1564.09,2076.48 1580.17,2092.56 1580.17,2102.19 1592.61,2114.64 U8.8@1592.61,2176.32 ; C33.1@1624.27,1445.35 1645.86,1466.94 1645.86,1497.1 1673.03,1524.28 U1.23@1716.36,1524.28 ; R51.2@1857.5,1198.5 1857.5,1069.23 1879.36,1047.37 ; 2215.59,755.84 2218,753.43
  Top Layer w16: VDD.1@1149.36,1555.77 1222.2,1555.77
  Top Layer w20: 1301.99,1442.44 1304.91,1445.35 C33.1@1621.27,1445.35 C33.1@1624.27,1445.35
  Top Layer w55: R66.1@1558.74,2071.12 v1(1545.74,2071.12) 1416.72,2071.12 1343.71,1998.11 C21.1@1200,1998.11 1200,1935.12 1221.71,1913.41 1221.71,1845.79 1222.5,1845 1222.2,1844.7 1222.2,1555.77 1222.2,1528.18 1301.99,1442.44 1529.08,1198.43 1728.3,1198.43 1857.5,1069.23 ; 1879.36,1047.37 2069.32,857.41 2280.65,857.41 ; C11.1@2215.59,700.3 2215.59,755.84 2215.59,785.86 L4.2@2213.09,788.36 2213.09,789.86 2280.65,857.41 ; D1.1@2460.95,886.04 2309.28,886.04 2280.65,857.41
  Bottom Layer w8: C20.1@1397.04,2043.97 1401.01,2043.97 C20.1@1422.6,2065.56 ; 1422.6,2079.4 1437.14,2093.94
  Bottom Layer w55: C20.1@1393.1,2047.5 1422.6,2079.4 ; 1430.31,2079.4 R67.2@1538.92,2079.4
VDD_PM: C22.1 L7.1 R66.2 R68.2 | length 377.7
  Top Layer w55: R66.2@1634.78,2076.48 1768.9,2076.48 L7.1@1908.77,2216.35 ; L7.1@1909.28,2234.86 L7.1@1909.28,2257.5
  Bottom Layer w8: R68.2@1642.61,2093.94 1643.41,2093.14 v1(1643.41,2071.12)
  other v1: 1896.79,2229.4 1896.79,2264.06
VOUT: C27.1 C29.1 C55.1 C58.1 C62.1 C63.1 L8.2 L10.1 R36.2 R95.2 TPH/TPL/BT.1 U11.5 VOUT.1 | length 5052.2
  Top Layer w20: C62.1@4672.18,1304.11 4672.18,1238.17 4672.18,1217.79 U11.5@4677.34,1212.63 ; C58.1@5055.82,1421.27 v4(5059.39,1417.7)
  Top Layer w40: C62.1@4690.09,1304.11 4857.41,1304.11 4974.57,1421.27 C58.1@5055.82,1421.27
  Signal Layer 2 w8: VOUT.1@3448.54,2512.5 3462.32,2498.72 3653.82,2498.72 3685.12,2467.42 TPH/TPL/BT.1@3685.12,2413.38
  Signal Layer 2 w30: TPH/TPL/BT.1@3685.12,2413.38 3977.19,2413.38 v1@4360,2030.56
  Signal Layer 2 w40: 3867.71,621.42 3932.66,621.42 4152.05,809.41 4152.05,1499.35 4360,1707.3 v1(4360,1897.3) v1(4360,1961.23) v1(4360,2021.18) v1@4360,2030.56
  Bottom Layer w50: C27.1@4337.42,1873.69 C29.1@4337.42,1994.54 4337.42,2021.18 4338.01,2021.77 4338.01,2043.32 v4@4491.83,2197.14 ; v4(5059.39,1417.7) 5087.77,1389.32 5087.77,1290.59 C55.1@5088.36,1290 C55.1@5088.36,1317.56
  Bottom Layer w100: v4@4491.83,2197.14 v4(4491.94,2197.25) v4(4658.24,2197.25) 4701.86,2197.25 4811.99,2087.12 4811.99,1591.77 4974.7,1429.06 5048.04,1429.06 v4(5059.39,1417.7)
  other v1: 3871.09,603.62 4673.9,1238.17
  other v4: 4581.41,2196.51
VSS: C11.2 C33.2 C48.2 D26.2 L6.2 Q11.1 Q11.2 Q11.3 R35.1 R37.1 R38.1 R59.1 U1.27 U1.28 U1.47 VSS1.1 VSS2.1 | length 2513
  Top Layer w8: v2(1764.59,1618.77) 1779.36,1604 1779.36,1539.92 1779.42,1539.85 1779.42,1535.3 1793.04,1521.68 U1.28@1794.81,1521.68
  Top Layer w20: R37.1@1506.5,1553.11 R38.1@1506.5,1619.6 R35.1@1506.5,1686.09
  Top Layer w55: L6.2@2213.09,543.47 C11.2@2213.09,626.34
  Signal Layer 1 w8: VSS1.1@1149.36,1392.85 1196.12,1439.6 1405.35,1439.6 1490.31,1524.57
  Signal Layer 1 w16: VSS2.1@1072.35,1727.16 1177.24,1727.16 1222.2,1682.2 1222.2,1645.33 1333.12,1534.41 v1(1503.55,1534.41)
  Signal Layer 1 w55: 1653.48,1295.75 1653.48,1273.25 2069.32,857.41 2181.82,857.41 2214.04,825.19 v1(2214.04,514.93)
  Bottom Layer w8: C48.2@1510.38,1635.68 R59.1@1579.6,1635.68 1579.6,1634.7 1623.35,1590.95 1650.93,1590.95 D26.2@1664.94,1576.94
  other v1: 1655.43,1309.8 1602.5,1512.95 1490.31,1581.65 1491.68,1632.73
  other v2: 1764.59,1571.52 1732.11,1618.77 1797.07,1618.77 1764.59,1666.01
pads on no net: H1.0 H2.0 H3.0 H4.0 I2C.1 I2C.2 I2C.3 I2C.4 I2C.7 I2C.8 Q1.0 Q2.0 Q3.0 Q4.0 SH-J1.0 SH-J2.0 SH-J4.0 U1.6 U1.10 U1.15 U1.16 U1.18 U1.19 U1.22 U1.25 U1.26 U1.29 U1.30 U1.36 U1.44 U3.1 U3.2

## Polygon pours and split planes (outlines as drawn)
PGND on Top Layer "TOP_LAYER_PGND_P032" (solid, pour order 32): 1230.78,2575 ccw(c1230.78,2506.72) 1182.5,2555 1132.41,2504.91 ccw(c1159.33,2477.99) 1121.26,2477.99 1121.26,1962.21 ccw(c1217.21,1962.21) 1149.36,1894.36 1245.61,1798.12 ccw(c1316.32,1868.83) 1316.32,1768.83 1762.11,1768.83 cw(c1762.11,1691.97) 1816.45,1746.32 cw(c1791.96,1721.82) 1826.6,1721.82 1826.6,1511.03 cw(c1763.73,1511.03) 1808.19,1466.58 1722.1,1380.49 cw(c1714.88,1387.71) 1714.88,1377.5 1704.37,1366.99 ccw(c1724.15,1347.21) 1696.18,1347.21 1696.18,1345.67 ccw(c1760.25,1345.67) 1714.94,1300.37 2256.95,758.36 cw(c2186.24,687.65) 2286.24,687.65 2286.24,152.68 ccw(c2386.24,152.68) 2315.53,81.97 2340.71,56.79 ccw(c2411.42,127.5) 2411.42,27.5 3086.62,27.5 ccw(c3086.62,82.31) 3125.37,43.55 3130.8,48.98 ccw(c3102.79,76.99) 3142.4,76.99 ccw(c3093.88,125.52) 3162.5,125.52 3162.5,2435.94 ccw(c3062.5,2435.94) 3133.21,2506.65 3094.15,2545.71 ccw(c3023.44,2475) 3023.44,2575 1479.47,2575
GND on Top Layer "TOP_LAYER_GND_P033" (solid, pour order 33): 3413.41,2575 ccw(c3413.41,2475) 3342.7,2545.71 3298.29,2501.3 ccw(c3369,2430.59) 3269,2430.59 3269,1563.6 ccw(c3369,1563.6) 3298.29,1492.89 cw(c3268.46,1463.06) 3310.64,1463.06 3310.64,890.24 ccw(c3410.64,890.24) 3339.93,819.53 3352.8,806.67 cw(c3320.74,774.61) 3366.07,774.61 3366.07,89.13 ccw(c3405.09,89.13) 3377.5,61.54 3383.74,55.3 ccw(c3454.45,126.01) 3454.45,26.01 5306.08,26.01 ccw(c5306.08,126.01) 5376.79,55.3 5397.43,75.94 ccw(c5330.88,142.5) 5425,142.5 5425,2484.06 ccw(c5377.29,2484.06) 5411.03,2517.79 5383.11,2545.71 ccw(c5312.4,2475) 5312.4,2575 3792.19,2575
VSS on Top Layer "TOP_LAYER_VSS_P019" (solid, pour order 19): 1459.27,1682.05 1459.27,1708.33 cw(c1476.79,1708.33) 1464.4,1720.72 1464.85,1721.17 cw(c1481.83,1704.18) 1481.83,1728.2 1761.35,1728.2 cw(c1761.35,1723.63) 1764.59,1726.86 cw(c1748.49,1710.77) 1771.26,1710.77 1771.26,1702.6 ccw(c1789.59,1702.6) 1776.63,1689.63 ccw(c1790.94,1703.95) 1790.94,1683.7 1801.79,1683.7 cw(c1801.79,1681.44) 1803.39,1683.04 cw(c1790.05,1669.71) 1808.91,1669.71 1808.91,1535.6 cw(c1761.09,1535.6) 1794.9,1501.79 1760.93,1467.81 cw(c1690.22,1538.52) 1690.22,1438.52 1686.33,1438.52 1678.03,1430.22 ccw(c1681.19,1427.06) 1676.72,1427.06 1676.72,1289.53 cw(c1652.86,1289.53) 1669.73,1272.65 cw(c1643.88,1298.5) 1643.88,1261.94 1627.06,1261.94 cw(c1627.06,1331.31) 1578.01,1282.26 1575.01,1285.26 cw(c1601.37,1311.62) 1564.09,1311.62 1564.09,1387.04 ccw(c1464.09,1387.04) 1534.8,1457.75 1488.56,1503.99 cw(c1559.27,1574.7) 1459.27,1574.7 1459.27,1682.24
NetC32_2 on Top Layer "TOP_LAYER_NETC32_2_P013" (solid, pour order 13): 3629.74,2118.1 3733.24,2118.1 cw(c3733.24,2097.81) 3747.59,2112.15 3785.51,2074.23 ccw(c3822.41,2111.13) 3822.41,2058.95 3987.13,2058.95 cw(c3987.13,2026.89) 4009.8,2049.56 4011.89,2047.46 cw(c4009.49,2045.06) 4012.89,2045.06 4012.89,1893.99 cw(c4003.48,1893.99) 4010.13,1887.34 cw(c3995.27,1902.2) 3995.27,1881.18 3855.38,1881.18 ccw(c3855.38,1781.18) 3784.67,1851.9 3778.33,1845.56 cw(c3710.32,1913.58) 3710.32,1817.39 3635.07,1817.39 cw(c3635.07,1849.31) 3612.5,1826.74 3610.04,1829.19 cw(c3649.1,1868.25) 3593.86,1868.25 3593.86,2056.35 cw(c3665.83,2056.35) 3614.94,2107.24 3623,2115.31 cw(c3629.74,2108.57)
